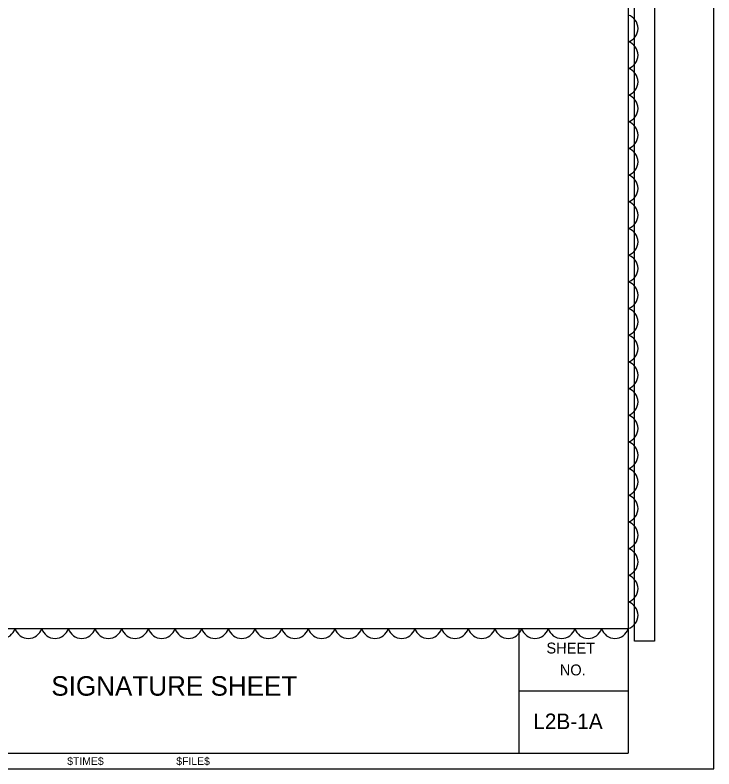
# Model space of a CAD drawing. Extents: x -811.3 to -790.1, y -2211.9 to -2188.9.
# Drawn here: x -799.322 to -794.836, y -2199.501 to -2194.665 of the extents above; entities that cross this region are included whole.
import ezdxf

# ---------------------------------------------------------------- set-up
doc = ezdxf.new("R2010")
doc.units = 0
for name, color, linetype in [('Cloud_dp', 7, 'Continuous'), ('PlotBorder_dp', 7, 'Continuous'), ('ScratchEle_dp', 7, 'Continuous'), ('SheetBorder_dp', 7, 'Continuous'), ('SheetLines_dp', 7, 'Continuous'), ('TextMinor', 7, 'Continuous'), ('TextMisc', 7, 'Continuous'), ('TextShtNo', 7, 'Continuous')]:
    doc.layers.add(name, color=color, linetype=linetype)

msp = doc.modelspace()

# ---------------------------------------------------------------- linework, layer by layer
at = {"layer": 'Cloud_dp'}
for centre, start, end in [((-795.4127, -2194.7504), 287.5, 72.5), ((-795.4127, -2194.9215), 287.5, 72.5), ((-795.4127, -2195.0926), 287.5, 72.5), ((-795.4127, -2195.2638), 287.5, 72.5), ((-795.4127, -2195.4349), 287.5, 72.5), ((-795.4127, -2195.606), 287.5, 72.5), ((-795.4127, -2195.7771), 287.5, 72.5), ((-795.4127, -2195.9482), 287.5, 72.5), ((-795.4127, -2196.1194), 287.5, 72.5), ((-795.4127, -2196.2905), 287.5, 72.5), ((-795.4127, -2196.4616), 287.5, 72.5), ((-795.4127, -2196.6327), 287.5, 72.5), ((-795.4127, -2196.8039), 287.5, 72.5), ((-795.4127, -2196.975), 287.5, 72.5), ((-795.4127, -2197.1461), 287.5, 72.5), ((-795.4127, -2197.3172), 287.5, 72.5), ((-795.4127, -2197.4883), 287.5, 72.5), ((-795.4127, -2197.6595), 287.5, 72.5), ((-795.4127, -2197.8306), 287.5, 72.5), ((-795.4127, -2198.0017), 287.5, 72.5), ((-795.4127, -2198.1728), 287.5, 72.5), ((-795.4127, -2198.344), 287.5, 72.5), ((-795.4127, -2198.5151), 287.5, 72.5), ((-799.4071, -2198.5737), 197.5, 342.5), ((-799.236, -2198.5737), 197.5, 342.5), ((-799.0649, -2198.5737), 197.5, 342.5), ((-798.8938, -2198.5737), 197.5, 342.5), ((-798.7227, -2198.5737), 197.5, 342.5), ((-798.5515, -2198.5737), 197.5, 342.5), ((-798.3804, -2198.5737), 197.5, 342.5), ((-798.2093, -2198.5737), 197.5, 342.5), ((-798.0382, -2198.5737), 197.5, 342.5), ((-797.867, -2198.5737), 197.5, 342.5), ((-797.6959, -2198.5737), 197.5, 342.5), ((-797.5248, -2198.5737), 197.5, 342.5), ((-797.3537, -2198.5737), 197.5, 342.5), ((-797.1826, -2198.5737), 197.5, 342.5), ((-797.0114, -2198.5737), 197.5, 342.5), ((-796.8403, -2198.5737), 197.5, 342.5), ((-796.6692, -2198.5737), 197.5, 342.5), ((-796.4981, -2198.5737), 197.5, 342.5), ((-796.3269, -2198.5737), 197.5, 342.5), ((-796.1558, -2198.5737), 197.5, 342.5), ((-795.9847, -2198.5737), 197.5, 342.5), ((-795.8136, -2198.5737), 197.5, 342.5), ((-795.6425, -2198.5737), 197.5, 342.5), ((-795.4713, -2198.5737), 197.5, 342.5)]:
    msp.add_arc(centre, 0.0897, start, end, dxfattribs=at)
at = {"layer": 'PlotBorder_dp'}
msp.add_lwpolyline([(-811.3358, -2199.5006), (-794.8358, -2199.5006), (-794.8358, -2188.9006), (-811.3358, -2188.9006)], close=True, dxfattribs=at)
at = {"layer": 'ScratchEle_dp'}
msp.add_lwpolyline([(-795.3456, -2191.8382), (-795.218, -2191.8382), (-795.218, -2198.6801), (-795.3456, -2198.6801)], close=True, dxfattribs=at)
at = {"layer": 'SheetBorder_dp'}
for p, q in [((-795.3858, -2189.0006), (-795.3858, -2199.4006)), ((-810.7858, -2198.6006), (-795.3858, -2198.6006)), ((-810.7858, -2199.4006), (-795.3858, -2199.4006))]:
    msp.add_line(p, q, dxfattribs=at)
at = {"layer": 'SheetLines_dp'}
for p, q in [((-796.0858, -2199.4006), (-796.0858, -2198.6006)), ((-796.0858, -2199.0006), (-795.3858, -2199.0006))]:
    msp.add_line(p, q, dxfattribs=at)

# ---------------------------------------------------------------- texts
at = {"layer": 'TextMinor'}
for s, p in [('$TIME$', (-798.9868, -2199.4756)), ('$FILE$', (-798.2868, -2199.4756))]:
    msp.add_text(s, height=0.05, rotation=360, dxfattribs=at).set_placement(p)
at = {"layer": 'TextMisc'}
for s, p in [('SHEET', (-795.911, -2198.7601)), ('NO.', (-795.8253, -2198.9003))]:
    msp.add_text(s, height=0.07, rotation=359.8607, dxfattribs=at).set_placement(p)
msp.add_text('       SIGNATURE SHEET         ', height=0.125, dxfattribs=at).set_placement((-799.414, -2199.0309))
at = {"layer": 'TextShtNo'}
msp.add_text('L2B-1A', height=0.1, dxfattribs=at).set_placement((-795.9956, -2199.2455))

doc.saveas('drawing.dxf')
